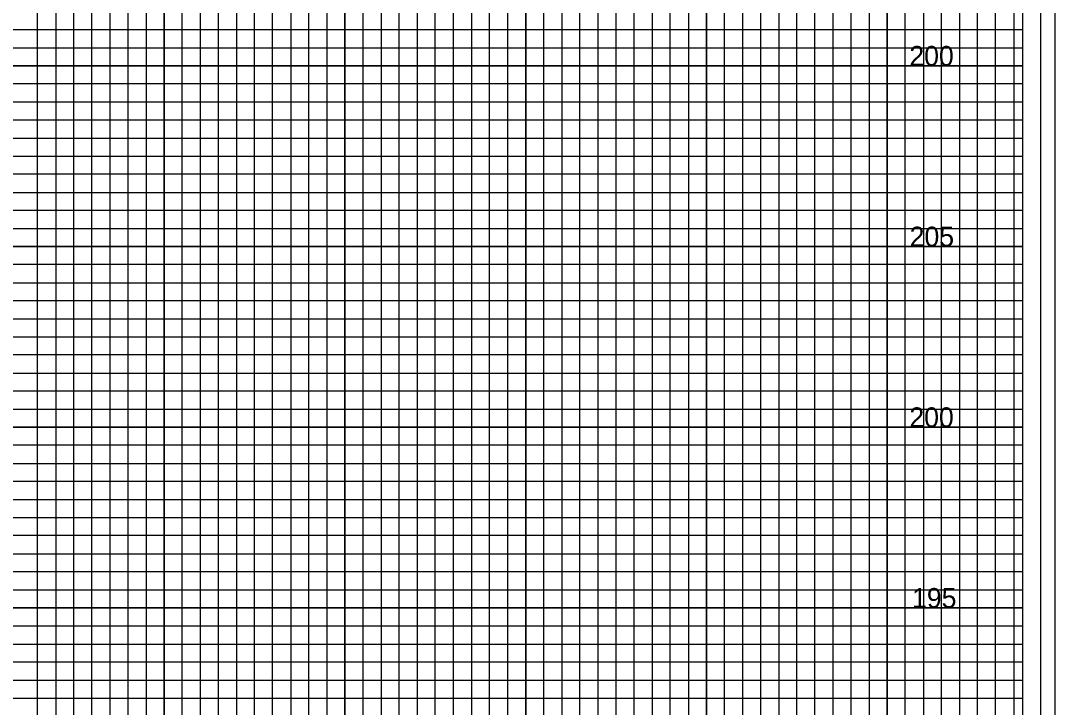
# Model space of a CAD drawing. Extents: x -4 to 103, y -2 to 351.
# Drawn here: x 74.78 to 103.4, y 32.25 to 51.25 of the extents above; entities that cross this region are included whole.
import ezdxf

# ---------------------------------------------------------------- set-up
doc = ezdxf.new("R2010")
doc.units = 0
for name, color, linetype in [('Old_Level_10', 7, 'Continuous'), ('Old_Level_4', 7, 'Continuous'), ('Old_Level_5', 7, 'Continuous'), ('Old_Level_6', 7, 'Continuous'), ('Old_Level_8', 7, 'Continuous'), ('Prop XS Finish Grade', 7, 'Continuous'), ('Prop XS SE Text', 7, 'Continuous')]:
    doc.layers.add(name, color=color, linetype=linetype)

msp = doc.modelspace()

# ---------------------------------------------------------------- linework, layer by layer
at = {"layer": 'Old_Level_10'}
for p, q in [((91.25, 0), (91.25, 63.425)), ((93.75, 0), (93.75, 63.425)), ((96.25, 0), (96.25, 63.425)), ((98.75, 0), (98.75, 63.425)), ((101.25, 0), (101.25, 63.425)), ((76.25, 0), (76.25, 62)), ((78.75, 0), (78.75, 62)), ((81.25, 0), (81.25, 62)), ((83.75, 0), (83.75, 62)), ((86.25, 0), (86.25, 62)), ((88.75, 0), (88.75, 62)), ((0, 50), (102.5, 50)), ((0, 47.5), (102.5, 47.5)), ((0, 45), (102.5, 45)), ((0, 42.5), (102.5, 42.5)), ((0, 40), (102.5, 40)), ((0, 37.5), (102.5, 37.5)), ((0, 35), (102.5, 35)), ((0, 32.5), (102.5, 32.5))]:
    msp.add_line(p, q, dxfattribs=at)
at = {"layer": 'Old_Level_4'}
for points in [[(90.25, 0), (90.25, 63.425), (90.75, 63.425), (90.75, 0)], [(91.75, 0), (91.75, 63.425), (92.25, 63.425), (92.25, 0)], [(92.75, 0), (92.75, 63.425), (93.25, 63.425), (93.25, 0)], [(94.25, 0), (94.25, 63.425), (94.75, 63.425), (94.75, 0)], [(95.25, 0), (95.25, 63.425), (95.75, 63.425), (95.75, 0)], [(96.75, 0), (96.75, 63.425), (97.25, 63.425), (97.25, 0)], [(97.75, 0), (97.75, 63.425), (98.25, 63.425), (98.25, 0)], [(99.25, 0), (99.25, 63.425), (99.75, 63.425), (99.75, 0)], [(100.25, 0), (100.25, 63.425)], [(100.25, 63.425), (100.75, 63.425), (100.75, 0), (101.75, 0), (101.75, 63.425), (102.25, 63.425), (102.25, 0)], [(75.25, 0), (75.25, 62), (75.75, 62), (75.75, 0)], [(76.75, 0), (76.75, 62), (77.25, 62), (77.25, 0)], [(77.75, 0), (77.75, 62), (78.25, 62), (78.25, 0)], [(79.25, 0), (79.25, 62), (79.75, 62), (79.75, 0)], [(80.25, 0), (80.25, 62), (80.75, 62), (80.75, 0)], [(81.75, 0), (81.75, 62), (82.25, 62), (82.25, 0)], [(82.75, 0), (82.75, 62), (83.25, 62), (83.25, 0)], [(84.25, 0), (84.25, 62), (84.75, 62), (84.75, 0)], [(85.25, 0), (85.25, 62), (85.75, 62), (85.75, 0)], [(86.75, 0), (86.75, 62), (87.25, 62), (87.25, 0)], [(87.75, 0), (87.75, 62), (88.25, 62), (88.25, 0)], [(89.25, 0), (89.25, 62), (89.75, 62), (89.75, 0)], [(0, 50.5), (102.5, 50.5), (102.5, 51), (0, 51)], [(0, 49), (102.5, 49), (102.5, 49.5), (0, 49.5)], [(0, 48), (102.5, 48), (102.5, 48.5), (0, 48.5)], [(0, 46.5), (102.5, 46.5), (102.5, 47), (0, 47)], [(0, 45.5), (102.5, 45.5), (102.5, 46), (0, 46)], [(0, 44), (102.5, 44), (102.5, 44.5), (0, 44.5)], [(0, 43), (102.5, 43), (102.5, 43.5), (0, 43.5)], [(0, 41.5), (102.5, 41.5), (102.5, 42), (0, 42)], [(0, 40.5), (102.5, 40.5), (102.5, 41), (0, 41)], [(0, 39), (102.5, 39), (102.5, 39.5), (0, 39.5)], [(0, 38), (102.5, 38), (102.5, 38.5), (0, 38.5)], [(0, 36.5), (102.5, 36.5), (102.5, 37), (0, 37)], [(0, 35.5), (102.5, 35.5), (102.5, 36), (0, 36)], [(0, 34), (102.5, 34), (102.5, 34.5), (0, 34.5)], [(0, 33), (102.5, 33), (102.5, 33.5), (0, 33.5)]]:
    msp.add_lwpolyline(points, dxfattribs=at)
at = {"layer": 'Old_Level_5'}
msp.add_lwpolyline([(103.4, 67.4), (-3.5, 67.4), (-3.5, -2.425), (103.4, -2.425)], close=True, dxfattribs=at)
at = {"layer": 'Old_Level_6'}
msp.add_lwpolyline([(102.5, 65), (0, 65), (0, 0), (102.5, 0)], close=True, dxfattribs=at)
at = {"layer": 'Old_Level_8'}
for points in [[(91.25, 0), (91.25, 63.425), (93.75, 63.425), (93.75, 0)], [(96.25, 0), (96.25, 63.425), (98.75, 63.425), (98.75, 0)], [(101.25, 0), (101.25, 63.425)], [(76.25, 0), (76.25, 62), (78.75, 62), (78.75, 0)], [(81.25, 0), (81.25, 62), (83.75, 62), (83.75, 0)], [(86.25, 0), (86.25, 62), (88.75, 62), (88.75, 0)], [(0, 47.5), (102.5, 47.5), (102.5, 50), (0, 50)], [(0, 42.5), (102.5, 42.5), (102.5, 45), (0, 45)], [(0, 37.5), (102.5, 37.5), (102.5, 40), (0, 40)], [(0, 32.5), (102.5, 32.5), (102.5, 35), (0, 35)]]:
    msp.add_lwpolyline(points, dxfattribs=at)
at = {"layer": 'Prop XS SE Text'}
msp.add_lwpolyline([(103, 66), (-2.8, 66), (-2.8, -1), (103, -1)], close=True, dxfattribs=at)

# ---------------------------------------------------------------- texts
at = {"layer": 'Prop XS Finish Grade'}
for s, p in [('200', (99.3638, 50)), ('205', (99.3724, 45)), ('200', (99.3638, 40)), ('195', (99.4383, 35))]:
    msp.add_text(s, height=0.55, dxfattribs=at).set_placement(p)

doc.saveas('drawing.dxf')
